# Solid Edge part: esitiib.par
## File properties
Author: Georg
Template: Iso Part.par
Last saved by: Kalle
Revision: 5
Application: Solid Edge
Accuracy: 0,990
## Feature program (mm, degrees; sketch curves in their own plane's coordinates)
sketch for "unnamed Protrusion 1" plane through (0, 0, 0) normal (0, 0, 1) x-axis (1, 0, 0)
  line (-32.5, -10) -> (32.5, -10)
  line (32.5, -10) -> (32.5, 2)
  line (12.5, 10) -> (32.5, 2)
  line (12.5, 10) -> (-12.5, 10)
  line (-12.5, 10) -> (-32.5, 2)
  line (-32.5, 2) -> (-32.5, -10)
  dimension (linear) = 32.5
  dimension (linear) = 32.5
extrude "unnamed Protrusion 1" add finite 3 along +normal
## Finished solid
Body 1: solid body, 8 faces, 18 edges, 12 vertices.
  Faces by surface: plane 8
  Edges by curve: line 18
Bounding box of the edges (mm): 65.000 x 20.000 x 3.000, from (-32.5, -10, 0) to (32.5, 10, 3).
Planar faces by outward normal: +x 1, +y 1, +z 1, -x 1, -y 1, -z 1, oblique 2
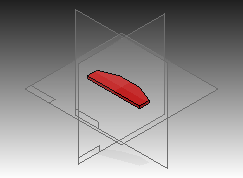
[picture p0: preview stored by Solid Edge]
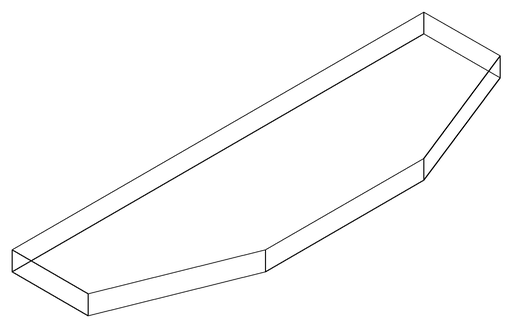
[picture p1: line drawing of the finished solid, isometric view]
